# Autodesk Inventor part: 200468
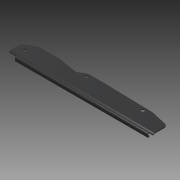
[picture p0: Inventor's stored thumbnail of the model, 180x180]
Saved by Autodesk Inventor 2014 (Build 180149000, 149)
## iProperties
Created: 2007-10
Part Number: 200468
Document SubType Name: Modeling
Designer: TH
Density: 7.85 g/cm^3
Mass: 510.334 g
Surface Area: 671.811 cm^2
Volume: 65.0106 cm^3
Material: Steel
Description: RAIL SIDE - RIGHT OUTER
Appearance: Dark Gray
Component Category: Lower Component
Author: TH
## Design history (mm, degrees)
sketch "Sketch1"
  geometry: L1 (0, -50.842)-(0, -19.842); L2 (0, -19.842)-(35, 0); L3 (35, 0)-(94, 0); L4 (94, 0)-(157, -9.978); L5 (157, -9.978)-(181, 4); L6 (181, 4)-(221, 4); L7 (221, 4)-(380, 0); L8 (380, 0)-(437, -12.842); L9 (0, -50.842)-(437, -50.842); L10 (0, 14.968)-(0, -61.811) reference; L11 (-87.4, 0)-(524.4, 0) reference; L12 (437, -50.842)-(437, -12.842); 1 further point
  constraints: 20 end point, 2 collinear, 2 point on line, 1 parallel, 1 perpendicular
  dimensions: "d0" = 50.84228 distance from line of point (0, 0) L9; "d1" = 31 distance of L1.start L1.end; "d2" = 35 distance of L2.end point (0, 0); "d3" = 59 distance of L2.end L3.end; "d4" = 9 deg angle of L3 L4; "d8" = 4 distance between parallel lines of L6 L3; "d9" = 40 distance of L5.end L6.end; "d12" = 38 distance of L9.end L8.end; "d13" = 57 distance from line of L7.end L12; "d14" = 437 distance between parallel lines of L12 L1; "d15" = 63 horizontal distance of L3.end L4.end; "d16" = 24 horizontal distance of L5.end L4.end
extrude "Extrusion1" new body sketch "Sketch1" distance "d17" = 2; taper "d18" = 0 deg
fillet "Fillet1" dims "d19" = 12
sketch "Sketch2"
  geometry: L1 (0, 24.009)-(0, 0) reference; L2 (2, 0)-(0, 0) reference; L3 (2, 24.009)-(2, 0) reference; L4 (0, 0)-(0, 0); L5 (-2, -4.472)-(-2, -6.75); L6 (-4, -8.75)-(-9, -8.75); L7 (-11, -6.75)-(-11, -1.3); L8 (-11, -1.3)-(-13, -1.3); L9 (-13, -1.3)-(-13, -6.75); L10 (-9, -10.75)-(-4, -10.75); L11 (0, -6.75)-(0, -4.472); L12 (0, -4)-(-2, -4); L13 (2, 0)-(2, 0); A1 r 4 centre (-2, 0) between (0.667, -2.981) and (2, 0); A2 r 2 centre (2, -4.472) between (0.667, -2.981) and (0, -4.472); A3 r 2 centre (-2, 0) between (-0.667, -1.491) and (0, 0); A4 r 4 centre (2, -4.472) between (-0.667, -1.491) and (-2, -4.472); A5 r 2 centre (-4, -6.75) between (-4, -8.75) and (-2, -6.75); A6 r 2 centre (-9, -6.75) between (-11, -6.75) and (-9, -8.75); A7 r 4 centre (-9, -6.75) between (-13, -6.75) and (-9, -10.75); A8 r 4 centre (-4, -6.75) between (-4, -10.75) and (0, -6.75); 1 further point
  constraints: 20 end point, 17 point on circle, 15 tangent, 8 centre point, 5 parallel, 2 collinear, 1 equal radius, 1 point on line
  dimensions: "d21" = 2 distance between parallel lines of L5 L11; "d22" = 2 distance between parallel lines of L10 L6 (= d21); "d23" = 2 distance between parallel lines of L9 L7 (= d21); "d24" = 9 distance between parallel lines of L7 L5; "d25" = 4.75 distance between parallel lines of L6 L12; "d26" = 4 distance between parallel lines of L2 L12; "d27" = 4 radius of A1; "d28" = 4 radius of A7; "d31" = 2 radius of A2; "d32" = 4 radius of A4; "d33" = 2 radial gap between concentric circles of A3 A1; "d34" = 2 radius of A3; "d35" = 2 radius of A5; "d36" = 2 radius of A6
extrude "Extrusion2" join sketch "Sketch2" distance "d29" = 437; taper "d30" = 0 deg
sketch "Sketch3"
  geometry: L1 (-2, -28.481)-(-2, -30.759) reference; L2 (-4, -32.759)-(-9, -32.759) reference; L3 (-11, -30.759)-(-11, -25.309) reference; L4 (-11, -25.309)-(-13, -25.309) reference; L5 (-13, -25.309)-(-13, -30.759) reference; L6 (-9, -34.759)-(-4, -34.759) reference; L7 (0, -30.759)-(0, -28.481) reference; L8 (0, -29.62)-(-2, -29.62); A1 r 2 centre (-4, -30.759) between (-4, -32.759) and (-2, -30.759) reference; A2 r 2 centre (-9, -30.759) between (-11, -30.759) and (-9, -32.759) reference; A3 r 4 centre (-9, -30.759) between (-13, -30.759) and (-9, -34.759) reference; A4 r 4 centre (-4, -30.759) between (-4, -34.759) and (0, -30.759) reference; 1 further point
  constraints: 2 end point, 2 midpoint
extrude "Extrusion3" cut sketch "Sketch3" distance "d37" = 23; taper "d38" = 0 deg
fillet "Fillet2" dims "d39" = 2
fillet "Fillet3" dims "d40" = 4
sketch "Sketch4"
  geometry: L1 (2, -35.153)-(2, -32.875) reference; L2 (11, -39.153)-(6, -39.153) reference; L3 (15, -29.703)-(15, -35.153) reference; L4 (13, -29.703)-(15, -29.703) reference; L5 (13, -35.153)-(13, -29.703) reference; L6 (6, -37.153)-(11, -37.153) reference; L7 (4, -32.875)-(4, -35.153) reference; L8 (2, -34.014)-(4, -34.014); A1 r 4 centre (6, -35.153) between (2, -35.153) and (6, -39.153) reference; A2 r 4 centre (11, -35.153) between (11, -39.153) and (15, -35.153) reference; A3 r 2 centre (11, -35.153) between (11, -37.153) and (13, -35.153) reference; A4 r 2 centre (6, -35.153) between (4, -35.153) and (6, -37.153) reference; 1 further point
  constraints: 2 end point, 2 midpoint
extrude "Extrusion4" cut sketch "Sketch4" distance "d41" = 12; taper "d42" = 0 deg
fillet "Fillet4" dims "d43" = 4
fillet "Fillet5" dims "d44" = 2
sketch "Sketch5"
  geometry: 4 further points
  dimensions: "d45" = 30.55 vertical distance of point (0, 0) point (21.897, -30.55); "d46" = 21.897 horizontal distance of point (0, 0) point (21.897, -30.55); "d47" = 185.717 horizontal distance of point (185.717, -6.53) point (0, 0); "d48" = 6.53 vertical distance of point (0, 0) point (185.717, -6.53); "d49" = 360.08 horizontal distance of point (360.08, -9.67) point (0, 0); "d50" = 9.67 vertical distance of point (0, 0) point (360.08, -9.67)
hole "Hole1" sketch "Sketch5" diameter "d51" = 10; stored, may be unused: countersink angle "d55" = 90 deg, drill point angle "d57" = 118 deg; dims "d52" = 6, "d53" = 4, "d54" = 2, "d56" = 8
hole "Hole2" sketch "Sketch5" diameter "d58" = 8.15; stored, may be unused: countersink angle "d62" = 90 deg, drill point angle "d64" = 118 deg; dims "d59" = 6, "d60" = 4, "d61" = 2, "d63" = 8
body "Solid1"
